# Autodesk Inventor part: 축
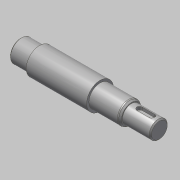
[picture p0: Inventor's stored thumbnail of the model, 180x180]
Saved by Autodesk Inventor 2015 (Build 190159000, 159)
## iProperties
Created: 2016-06
Part Number: 축
Material: 강철, 연강
Document SubType Name: Modeling
Designer: mduedu
Density: 7.86 g/cm^3
Appearance: 강철
Author: mduedu
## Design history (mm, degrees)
sketch "스케치1"
  geometry: L1 (-62, 0)-(62, 0); L2 (-62, 0)-(-62, 10); L3 (-62, 10)-(-45, 10); L4 (-45, 10)-(-45, 12); L5 (-45, 12)-(9, 12); L6 (9, 12)-(9, 10); L7 (9, 10)-(37, 10); L8 (37, 10)-(37, 8); L9 (37, 8)-(62, 8); L10 (62, 8)-(62, 0); 2 further points
  constraints: 20 end point, 5 parallel, 2 perpendicular, 1 coincident, 1 collinear, 1 horizontal, 1 midpoint, 1 vertical
  dimensions: "d0" = 124 distance of L1.start L1.end; "d2" = 16 diameter of L9 L1; "d3" = 20 diameter of L7 L1; "d4" = 24 diameter of L5 L1; "d5" = 20 diameter of L3 L1; "d6" = 17 distance of L2.end L3.end; "d7" = 25 distance of L8.end L9.end; "d8" = 53 distance from line of L5.end L10
revolve "회전1" sketch "스케치1" stored, may be unused: angle "d9" = 90 deg
chamfer "모따기1" distance "d10" = 2; stored, may be unused: second distance "d11" = 2, angle "d12" = 30 deg
fillet "모깎기1" dims "d13" = 2
node "작업 평면1"
sketch "스케치2"
  geometry: L1 (-5, 2.5)-(6, 2.5); L2 (6, -2.5)-(-5, -2.5); L3 (-5, 0)-(6, 0); L4 (-12.5, 8.845)-(-12.5, -8.845) reference; A1 r 2.5 centre (-5, 0) between (-5, 2.5) and (-5, -2.5); A2 r 2.5 centre (6, 0) between (6, -2.5) and (6, 2.5); 1 further point
  constraints: 6 end point, 4 point on circle, 3 tangent, 2 centre point, 2 parallel, 1 horizontal, 1 horizontal alignment
  dimensions: "d14" = 5 distance edge to line of A1 L4; "d15" = 5 distance between parallel lines of L2 L1; "d16" = 16 dimension on A2 A1
extrude "돌출1" cut sketch "스케치2" distance "d17" = 3; taper "d18" = 0 deg
chamfer "모따기2" distance "d19" = 1; stored, may be unused: second distance "d20" = 2, angle "d21" = 30 deg
sketch "스케치3"
  geometry: L1 (-37, -8)-(-61, -8) reference; L2 (-62, -7)-(-62, 7) reference; L3 (-38.5, -8)-(-40, -6.5); L4 (-40, -6.5)-(-40, -8); L5 (-38.5, -8)-(-40, -8); 1 further point
  constraints: 6 end point, 2 point on line, 1 collinear, 1 vertical
  dimensions: "d22" = 45 deg angle of L4 L3; "d23" = 22 distance between parallel lines of L2 L4; "d24" = 3 diameter of L3.start L4
revolve "회전2" stored, may be unused: angle "d25" = 90 deg
node "작업점1"
sketch "스케치4"
  geometry: 1 further point
hole "구멍1" sketch "스케치4" at (0, 0) diameter "d26" = 3.242; stored, may be unused: countersink angle "d30" = 90 deg, drill point angle "d32" = 120 deg; dims "d27" = 8, "d28" = 4, "d29" = 2, "d31" = 11
chamfer "모따기3" distance "d33" = 2; stored, may be unused: second distance "d34" = 2, angle "d35" = 30 deg
node "솔리드1"
